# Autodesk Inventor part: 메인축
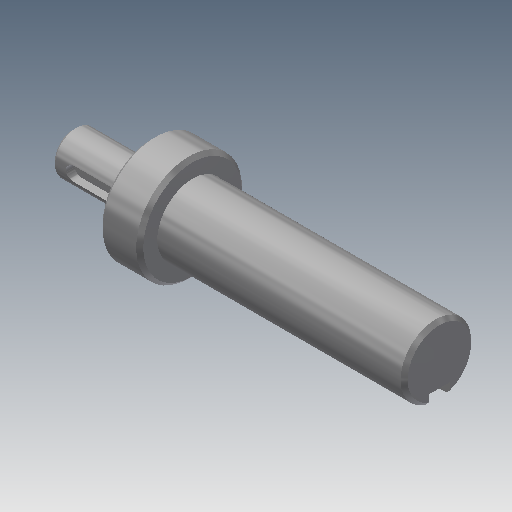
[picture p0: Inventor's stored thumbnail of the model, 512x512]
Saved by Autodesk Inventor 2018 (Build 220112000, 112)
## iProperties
Created: 2018-09
Part Number: 메인축
Document SubType Name: Modeling
Density: 7.86 g/cm^3
Material: 강철, 연강
Mass: 251.954 g
Surface Area: 77.4403 cm^2
Volume: 32.0552 cm^3
Appearance: 강철
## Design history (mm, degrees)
sketch "스케치1"
  geometry: L1 (34.997, -37.5)-(34.997, -77.5) reference; L2 (46.5, -38.401)-(46.5, -76.599) reference; L3 (12.497, -57.5)-(116.5, -57.5); L4 (12.497, -63.5)-(34.997, -63.5); L5 (34.997, -72.5)-(46.5, -72.5); L6 (46.5, -67.5)-(116.5, -67.5); L7 (116.5, -67.5)-(116.5, -57.5); L8 (12.497, -63.5)-(12.497, -57.5); 2 further points
  constraints: 12 end point, 5 point on line, 4 perpendicular, 1 midpoint, 1 parallel
  dimensions: "d0" = 20 diameter of L6 L3; "d1" = 30 diameter of L5 L3; "d2" = 22.5 distance of L4.start L4.end; "d3" = 70 distance of L6.start L6.end; "d5" = 12 diameter of L4 L3
revolve "회전1" sketch "스케치1" stored, may be unused: angle "d4" = 90 deg
chamfer "모따기1" distance "d6" = 1; stored, may be unused: second distance "d7" = 2, angle "d8" = 45 deg
node "작업 평면1"
sketch "스케치2"
  geometry: L1 (-11.25, -5)-(-11.25, 5) reference; L2 (-5.25, 2)-(4.75, 2); L3 (4.75, -2)-(-5.25, -2); A1 r 2 centre (4.75, 0) between (4.75, -2) and (4.75, 2); A2 r 2 centre (-5.25, 0) between (-5.25, 2) and (-5.25, -2); 2 further points
  constraints: 4 end point, 4 point on circle, 4 tangent, 2 centre point, 1 horizontal alignment, 1 midpoint, 1 parallel, 1 perpendicular
  dimensions: "d9" = 4 distance between parallel lines of L3 L2; "d10" = 14 dimension on A1 A2; "d11" = 4 distance edge to line of A2 L1
extrude "돌출1" cut sketch "스케치2" distance "d12" = 2.5; taper "d13" = 0 deg
node "작업 평면2"
sketch "스케치3"
  geometry: L1 (35, 9)-(35, -9) reference; L2 (35, 3)-(20, 3); L3 (20, -3)-(35, -3); A1 r 3 centre (20, 0) between (20, 3) and (20, -3); 2 further points
  constraints: 4 end point, 2 perpendicular, 2 point on circle, 2 point on line, 2 tangent, 1 centre point, 1 horizontal alignment, 1 midpoint
  dimensions: "d14" = 6 distance between parallel lines of L3 L2; "d15" = 18 dimension on A1 L1
extrude "돌출2" cut sketch "스케치3" distance "d16" = 3.5; taper "d17" = 0 deg
node "솔리드1"
node "참조1"
node "참조2"
